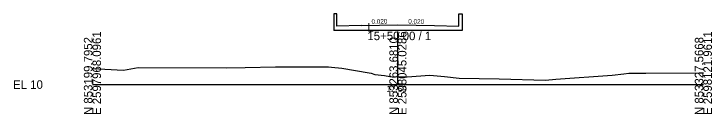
# Model space of a CAD drawing. Extents: x -26 to 1203, y -10 to 9526.
# Drawn here: x -25.7 to 202.8, y 5490.3 to 5523.2 of the extents above; entities that cross this region are included whole.
import ezdxf

# ---------------------------------------------------------------- set-up
doc = ezdxf.new("R2010")
doc.units = 0
for name, color, linetype in [('Exist Cross Section Cell', 7, 'Continuous'), ('Exist XS Center Line Elevation Label', 7, 'Continuous'), ('Exist XS Ground Line', 7, 'Continuous'), ('Prop XS Bridge', 7, 'Continuous'), ('Prop XS SE Text', 7, 'Continuous')]:
    doc.layers.add(name, color=color, linetype=linetype)

msp = doc.modelspace()

# ---------------------------------------------------------------- linework, layer by layer
at = {"layer": 'Exist Cross Section Cell'}
for p, q in [((100, 5500), (100, 5517.39)), ((0, 5500), (100, 5500)), ((100, 5500), (200, 5500))]:
    msp.add_line(p, q, dxfattribs=at)
at = {"layer": 'Exist XS Ground Line'}
for p, q in [((10.17, 5504.68), (14.97, 5505.56)), ((14.97, 5505.56), (43.76, 5505.49)), ((43.76, 5505.49), (49.97, 5505.66)), ((49.97, 5505.66), (59.97, 5505.8)), ((59.97, 5505.8), (77.29, 5505.78)), ((77.29, 5505.78), (78.31, 5505.73)), ((78.31, 5505.73), (81.67, 5505.42)), ((81.67, 5505.42), (90.6, 5503.9)), ((0, 5505.33), (10.17, 5504.68)), ((90.6, 5503.9), (91.3, 5503.77)), ((91.3, 5503.77), (92.5, 5503.29)), ((92.5, 5503.29), (95.65, 5502.96)), ((151.7, 5501.77), (170.16, 5503.08)), ((170.16, 5503.08), (174.01, 5503.57)), ((174.01, 5503.57), (175.58, 5503.8)), ((175.58, 5503.8), (181.13, 5503.8)), ((181.13, 5503.8), (198.66, 5503.81)), ((198.66, 5503.81), (200, 5503.83)), ((95.65, 5502.96), (97.32, 5502.66)), ((97.32, 5502.66), (100, 5502.59)), ((100, 5502.59), (103.07, 5502.51)), ((103.07, 5502.51), (110.48, 5503.04)), ((110.48, 5503.04), (115.23, 5502.63)), ((115.23, 5502.63), (120.08, 5502.07)), ((120.08, 5502.07), (133.11, 5501.84)), ((133.11, 5501.84), (148.33, 5501.46)), ((148.33, 5501.46), (151.7, 5501.77))]:
    msp.add_line(p, q, dxfattribs=at)
at = {"layer": 'Prop XS Bridge'}
for p, q in [((79, 5523.21), (79, 5517.79)), ((80, 5523.21), (79, 5523.21)), ((80, 5519.21), (80, 5523.21)), ((120, 5519.21), (120, 5523.21)), ((120, 5523.21), (121, 5523.21)), ((121, 5523.21), (121, 5517.79)), ((88, 5519.37), (80, 5519.21)), ((88, 5519.37), (100, 5519.61)), ((100, 5519.61), (112, 5519.37)), ((112, 5519.37), (120, 5519.21)), ((121, 5517.79), (79, 5517.79))]:
    msp.add_line(p, q, dxfattribs=at)

# ---------------------------------------------------------------- texts
at = {"layer": 'Exist Cross Section Cell'}
for s, p in [('L', (90, 5517.39)), ('15+50.00 / 1', (90, 5514.59)), ('EL 10', (-26, 5498.6))]:
    msp.add_text(s, height=2.8, dxfattribs=at).set_placement(p)
for s, p in [('E 2597968.0961', (2.8, 5490)), ('E 2598045.0286', (102.8, 5490)), ('E 2598121.9611', (202.8, 5490)), ('N 853199.7952', (0, 5490)), ('N 853263.6810', (100, 5490)), ('N 853327.5668', (200, 5490))]:
    msp.add_text(s, height=2.8, rotation=90, dxfattribs=at).set_placement(p)
at = {"layer": 'Exist XS Center Line Elevation Label'}
msp.add_text('12.59', height=2, dxfattribs=at).set_placement((96.26, 5497.59))
at = {"layer": 'Prop XS SE Text'}
for rotation, p in [(1.1458, (91.38, 5519.94)), (358.8542, (103.38, 5520.04))]:
    msp.add_text('0.020', height=1.5, rotation=rotation, dxfattribs=at).set_placement(p)

doc.saveas('drawing.dxf')
